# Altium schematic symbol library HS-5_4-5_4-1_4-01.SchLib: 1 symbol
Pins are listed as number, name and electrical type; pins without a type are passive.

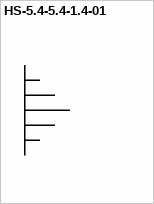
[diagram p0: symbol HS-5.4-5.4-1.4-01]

## HS-5.4-5.4-1.4-01
designator HS?
HEATSINK-5.4-5.4-1.4-01; Manufacturer: Custom Thermoelelctric; SymbolVersion: use current date i.e. 2008-05-20; SymbolCreator: A0412036; CompType: Used in some BOM reports.  Useful for finding later.; U/M: EACH
footprint HS-5_4-5-4_1_4-01 (HS5.4-5.4-1.4-01 HEATSINK cUSTOM THERMOELECTRIC)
